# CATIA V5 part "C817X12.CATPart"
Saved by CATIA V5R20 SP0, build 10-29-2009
Part number: C817X12
Source: Unknown
Property "A": "53.5"
Property "ARTICLENO": "C817XC12"
Property "B": "11"
Property "BOMINFO": "C817XC12"
Property "C": "11.0"
Property "CA": "C817XC12"
Property "D": "34"
Property "DES": "EYEBOLT TWISTER WITH BEARING M12 WITH KEY"
Property "E": "44"
Property "F": "32.0"
Property "K": "56"
Property "L": "18.0"
Property "LINA": "C817XC12"
Property "NB": "C817XC12"
Property "NBSYN": "$CODE."
Property "NN": "C817X"
Property "NT": "Eyebolt twister with bearing"
Property "SIZE": "M12"
Property "SUPPLIER": "CF"
Property "WEIGHT": "460"
Property "WLL": "0.75"
Bounding box of the stored display mesh (mm): x -27.988 to 27.988, y -18 to 64.5, z -23.619 to 23.619
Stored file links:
  C:\Users\Utente\Desktop\3D files 817X\C817X12.CATPart
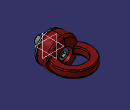
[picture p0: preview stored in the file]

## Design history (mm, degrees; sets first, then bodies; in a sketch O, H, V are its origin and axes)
Body1 "Geometry.1" (main body)
  Solid1 "C817XC12.catpart": solid without history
